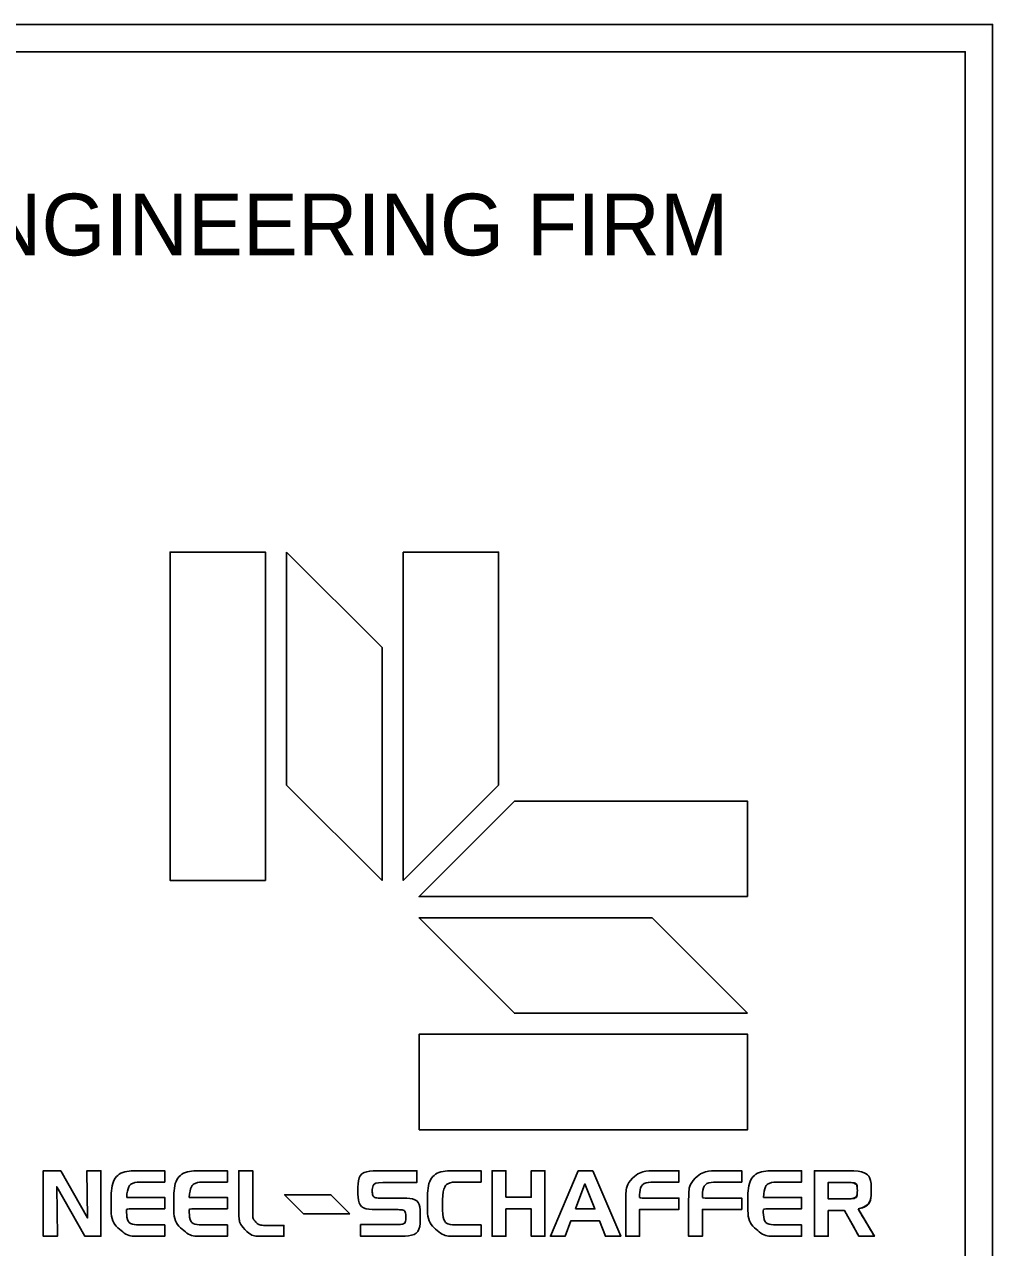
# Model space of a CAD drawing. Extents: x 1524103 to 2096450, y 1024229 to 1162569.
# Drawn here: x 2069965 to 2074608, y 1118769 to 1124635 of the extents above; entities that cross this region are included whole.
import ezdxf

# ---------------------------------------------------------------- set-up
doc = ezdxf.new("R2010")
doc.units = 0
for name, color, linetype in [('Default', 7, 'Continuous'), ('RD_SHT_Bndy', 7, 'Continuous'), ('RD_SHT_TX', 7, 'Continuous')]:
    doc.layers.add(name, color=color, linetype=linetype)

# ---------------------------------------------------------------- blocks, each defined once
blk = doc.blocks.new('block 3')
at = {"layer": 'Default'}
for p, q in [((-1.185, -5.553), (-1.185, -4.948)), ((-1.185, -4.948), (-1.024, -4.948)), ((-1.024, -4.948), (-0.776, -5.383)), ((-0.776, -5.383), (-0.782, -4.948)), ((-0.782, -4.948), (-0.653, -4.948)), ((-0.653, -4.948), (-0.653, -5.553)), ((2.958, -5.553), (2.958, -4.948)), ((2.958, -4.948), (3.085, -4.948)), ((3.085, -4.948), (3.085, -5.193)), ((3.318, -5.193), (3.318, -4.948)), ((3.318, -4.948), (3.445, -4.948)), ((3.445, -4.948), (3.445, -5.553)), ((3.496, -5.553), (3.752, -4.948)), ((3.752, -4.948), (3.887, -4.948)), ((3.887, -4.948), (4.145, -5.553)), ((3.814, -5.069), (3.726, -5.301)), ((3.906, -5.301), (3.814, -5.069)), ((-0.8, -5.553), (-1.06, -5.096)), ((-1.06, -5.096), (-1.054, -5.553)), ((1.47, -5.169), (1.042, -5.169)), ((1.042, -5.169), (1.217, -5.345)), ((1.646, -5.345), (1.47, -5.169)), ((3.085, -5.193), (3.318, -5.193)), ((3.318, -5.3), (3.085, -5.3)), ((3.085, -5.3), (3.085, -5.553)), ((3.318, -5.553), (3.318, -5.3)), ((3.726, -5.301), (3.906, -5.301)), ((1.217, -5.345), (1.646, -5.345)), ((3.685, -5.409), (3.631, -5.553)), ((3.948, -5.409), (3.685, -5.409)), ((4.003, -5.553), (3.948, -5.409)), ((-1.054, -5.553), (-1.185, -5.553)), ((-0.653, -5.553), (-0.8, -5.553)), ((3.085, -5.553), (2.958, -5.553)), ((3.445, -5.553), (3.318, -5.553)), ((3.631, -5.553), (3.496, -5.553)), ((4.145, -5.553), (4.003, -5.553))]:
    blk.add_line(p, q, dxfattribs=at)
for points in [[(-1.024, -4.948), (-0.776, -5.383), (-0.782, -4.948), (-0.653, -4.948), (-0.653, -5.553), (-0.8, -5.553), (-1.06, -5.096), (-1.054, -5.553), (-1.185, -5.553), (-1.185, -4.948), (-1.024, -4.948)], [(3.085, -5.193), (3.318, -5.193), (3.318, -4.948), (3.445, -4.948), (3.445, -5.553), (3.318, -5.553), (3.318, -5.3), (3.085, -5.3), (3.085, -5.553), (2.958, -5.553), (2.958, -4.948), (3.085, -4.948), (3.085, -5.193)], [(3.887, -4.948), (4.145, -5.553), (4.003, -5.553), (3.948, -5.409), (3.685, -5.409), (3.631, -5.553), (3.496, -5.553), (3.752, -4.948), (3.887, -4.948)], [(6.335, -5.3), (6.486, -5.553), (6.343, -5.553), (6.21, -5.315), (6.06, -5.315), (6.06, -5.553), (5.932, -5.553), (5.932, -4.948), (6.246, -4.948)], [(3.726, -5.301), (3.906, -5.301), (3.814, -5.069), (3.726, -5.301)], [(6.216, -5.056), (6.06, -5.056), (6.06, -5.208), (6.216, -5.208)], [(1.646, -5.345), (1.47, -5.169), (1.042, -5.169), (1.217, -5.345), (1.646, -5.345)]]:
    blk.add_lwpolyline(points, dxfattribs=at)
for points in [[(-0.415, -5.194), (-0.415, -5.194), (-0.063, -5.194), (-0.063, -5.194), (-0.063, -5.194), (-0.063, -5.299), (-0.063, -5.299), (-0.063, -5.299), (-0.416, -5.299), (-0.416, -5.299), (-0.415, -5.408), (-0.372, -5.448), (-0.272, -5.448), (-0.272, -5.448), (-0.063, -5.448), (-0.063, -5.448), (-0.063, -5.448), (-0.063, -5.553), (-0.063, -5.553), (-0.063, -5.553), (-0.278, -5.553), (-0.278, -5.553), (-0.351, -5.553), (-0.407, -5.547), (-0.466, -5.5), (-0.529, -5.45), (-0.559, -5.371), (-0.559, -5.262), (-0.559, -5.048), (-0.469, -4.948), (-0.274, -4.948), (-0.274, -4.948), (-0.063, -4.948), (-0.063, -4.948), (-0.063, -4.948), (-0.063, -5.053), (-0.063, -5.053), (-0.063, -5.053), (-0.272, -5.053), (-0.272, -5.053), (-0.364, -5.053), (-0.41, -5.099), (-0.415, -5.194)], [(-0.415, -5.194), (-0.415, -5.194), (-0.063, -5.194), (-0.063, -5.194), (-0.063, -5.194), (-0.063, -5.299), (-0.063, -5.299), (-0.063, -5.299), (-0.416, -5.299), (-0.416, -5.299), (-0.415, -5.408), (-0.372, -5.448), (-0.272, -5.448), (-0.272, -5.448), (-0.063, -5.448), (-0.063, -5.448), (-0.063, -5.448), (-0.063, -5.553), (-0.063, -5.553), (-0.063, -5.553), (-0.278, -5.553), (-0.278, -5.553), (-0.351, -5.553), (-0.407, -5.547), (-0.466, -5.5), (-0.529, -5.45), (-0.559, -5.371), (-0.559, -5.262), (-0.559, -5.048), (-0.469, -4.948), (-0.274, -4.948), (-0.274, -4.948), (-0.063, -4.948), (-0.063, -4.948), (-0.063, -4.948), (-0.063, -5.053), (-0.063, -5.053), (-0.063, -5.053), (-0.272, -5.053), (-0.272, -5.053), (-0.364, -5.053), (-0.41, -5.099), (-0.415, -5.194)], [(0.163, -5.194), (0.163, -5.194), (0.515, -5.194), (0.515, -5.194), (0.515, -5.194), (0.515, -5.299), (0.515, -5.299), (0.515, -5.299), (0.162, -5.299), (0.162, -5.299), (0.163, -5.408), (0.206, -5.448), (0.306, -5.448), (0.306, -5.448), (0.515, -5.448), (0.515, -5.448), (0.515, -5.448), (0.515, -5.553), (0.515, -5.553), (0.515, -5.553), (0.3, -5.553), (0.3, -5.553), (0.227, -5.553), (0.171, -5.547), (0.112, -5.5), (0.049, -5.45), (0.019, -5.371), (0.019, -5.262), (0.019, -5.048), (0.109, -4.948), (0.304, -4.948), (0.304, -4.948), (0.515, -4.948), (0.515, -4.948), (0.515, -4.948), (0.515, -5.053), (0.515, -5.053), (0.515, -5.053), (0.306, -5.053), (0.306, -5.053), (0.214, -5.053), (0.168, -5.099), (0.163, -5.194)], [(0.163, -5.194), (0.163, -5.194), (0.515, -5.194), (0.515, -5.194), (0.515, -5.194), (0.515, -5.299), (0.515, -5.299), (0.515, -5.299), (0.162, -5.299), (0.162, -5.299), (0.163, -5.408), (0.206, -5.448), (0.306, -5.448), (0.306, -5.448), (0.515, -5.448), (0.515, -5.448), (0.515, -5.448), (0.515, -5.553), (0.515, -5.553), (0.515, -5.553), (0.3, -5.553), (0.3, -5.553), (0.227, -5.553), (0.171, -5.547), (0.112, -5.5), (0.049, -5.45), (0.019, -5.371), (0.019, -5.262), (0.019, -5.048), (0.109, -4.948), (0.304, -4.948), (0.304, -4.948), (0.515, -4.948), (0.515, -4.948), (0.515, -4.948), (0.515, -5.053), (0.515, -5.053), (0.515, -5.053), (0.306, -5.053), (0.306, -5.053), (0.214, -5.053), (0.168, -5.099), (0.163, -5.194)], [(0.675, -5.49), (0.629, -5.441), (0.62, -5.388), (0.62, -5.308), (0.62, -5.308), (0.62, -4.948), (0.62, -4.948), (0.62, -4.948), (0.748, -4.948), (0.748, -4.948), (0.748, -4.948), (0.748, -5.28), (0.748, -5.28), (0.748, -5.288), (0.748, -5.296), (0.748, -5.304), (0.748, -5.353), (0.748, -5.39), (0.769, -5.413), (0.796, -5.445), (0.832, -5.453), (0.886, -5.453), (0.886, -5.453), (1.036, -5.453), (1.036, -5.453), (1.036, -5.453), (1.036, -5.553), (1.036, -5.553), (1.036, -5.553), (0.875, -5.553), (0.875, -5.553), (0.787, -5.553), (0.729, -5.547), (0.675, -5.49)], [(0.675, -5.49), (0.629, -5.441), (0.62, -5.388), (0.62, -5.308), (0.62, -5.308), (0.62, -4.948), (0.62, -4.948), (0.62, -4.948), (0.748, -4.948), (0.748, -4.948), (0.748, -4.948), (0.748, -5.28), (0.748, -5.28), (0.748, -5.288), (0.748, -5.296), (0.748, -5.304), (0.748, -5.353), (0.748, -5.39), (0.769, -5.413), (0.796, -5.445), (0.832, -5.453), (0.886, -5.453), (0.886, -5.453), (1.036, -5.453), (1.036, -5.453), (1.036, -5.453), (1.036, -5.553), (1.036, -5.553), (1.036, -5.553), (0.875, -5.553), (0.875, -5.553), (0.787, -5.553), (0.729, -5.547), (0.675, -5.49)], [(1.95, -5.056), (1.884, -5.056), (1.852, -5.08), (1.852, -5.135), (1.852, -5.179), (1.879, -5.201), (1.932, -5.201), (1.932, -5.201), (2.101, -5.201), (2.101, -5.201), (2.236, -5.201), (2.294, -5.245), (2.294, -5.372), (2.294, -5.499), (2.226, -5.553), (2.082, -5.553), (2.082, -5.553), (1.744, -5.553), (1.744, -5.553), (1.744, -5.553), (1.744, -5.445), (1.744, -5.445), (1.744, -5.445), (2.062, -5.445), (2.062, -5.445), (2.13, -5.445), (2.161, -5.429), (2.161, -5.377), (2.161, -5.323), (2.132, -5.307), (2.071, -5.307), (2.071, -5.307), (1.921, -5.307), (1.921, -5.307), (1.782, -5.307), (1.719, -5.255), (1.719, -5.133), (1.719, -5.002), (1.788, -4.948), (1.932, -4.948), (1.932, -4.948), (2.264, -4.948), (2.264, -4.948), (2.264, -4.948), (2.264, -5.056), (2.264, -5.056), (2.264, -5.056), (1.95, -5.056), (1.95, -5.056)], [(1.95, -5.056), (1.884, -5.056), (1.852, -5.08), (1.852, -5.135), (1.852, -5.179), (1.879, -5.201), (1.932, -5.201), (1.932, -5.201), (2.101, -5.201), (2.101, -5.201), (2.236, -5.201), (2.294, -5.245), (2.294, -5.372), (2.294, -5.499), (2.226, -5.553), (2.082, -5.553), (2.082, -5.553), (1.744, -5.553), (1.744, -5.553), (1.744, -5.553), (1.744, -5.445), (1.744, -5.445), (1.744, -5.445), (2.062, -5.445), (2.062, -5.445), (2.13, -5.445), (2.161, -5.429), (2.161, -5.377), (2.161, -5.323), (2.132, -5.307), (2.071, -5.307), (2.071, -5.307), (1.921, -5.307), (1.921, -5.307), (1.782, -5.307), (1.719, -5.255), (1.719, -5.133), (1.719, -5.002), (1.788, -4.948), (1.932, -4.948), (1.932, -4.948), (2.264, -4.948), (2.264, -4.948), (2.264, -4.948), (2.264, -5.056), (2.264, -5.056), (2.264, -5.056), (1.95, -5.056), (1.95, -5.056)], [(2.499, -5.267), (2.499, -5.402), (2.54, -5.448), (2.647, -5.448), (2.647, -5.448), (2.856, -5.448), (2.856, -5.448), (2.856, -5.448), (2.856, -5.553), (2.856, -5.553), (2.856, -5.553), (2.641, -5.553), (2.641, -5.553), (2.568, -5.553), (2.511, -5.547), (2.452, -5.5), (2.39, -5.45), (2.36, -5.371), (2.36, -5.262), (2.36, -5.048), (2.45, -4.948), (2.644, -4.948), (2.644, -4.948), (2.856, -4.948), (2.856, -4.948), (2.856, -4.948), (2.856, -5.052), (2.856, -5.052), (2.856, -5.052), (2.647, -5.052), (2.647, -5.052), (2.54, -5.052), (2.499, -5.117), (2.499, -5.267)], [(2.499, -5.267), (2.499, -5.402), (2.54, -5.448), (2.647, -5.448), (2.647, -5.448), (2.856, -5.448), (2.856, -5.448), (2.856, -5.448), (2.856, -5.553), (2.856, -5.553), (2.856, -5.553), (2.641, -5.553), (2.641, -5.553), (2.568, -5.553), (2.511, -5.547), (2.452, -5.5), (2.39, -5.45), (2.36, -5.371), (2.36, -5.262), (2.36, -5.048), (2.45, -4.948), (2.644, -4.948), (2.644, -4.948), (2.856, -4.948), (2.856, -4.948), (2.856, -4.948), (2.856, -5.052), (2.856, -5.052), (2.856, -5.052), (2.647, -5.052), (2.647, -5.052), (2.54, -5.052), (2.499, -5.117), (2.499, -5.267)], [(4.253, -5.017), (4.3, -4.969), (4.376, -4.948), (4.488, -4.948), (4.488, -4.948), (4.682, -4.948), (4.682, -4.948), (4.682, -4.948), (4.682, -5.053), (4.682, -5.053), (4.682, -5.053), (4.477, -5.053), (4.477, -5.053), (4.369, -5.053), (4.32, -5.096), (4.318, -5.201), (4.318, -5.201), (4.682, -5.201), (4.682, -5.201), (4.682, -5.201), (4.682, -5.305), (4.682, -5.305), (4.682, -5.305), (4.318, -5.305), (4.318, -5.305), (4.318, -5.305), (4.318, -5.553), (4.318, -5.553), (4.318, -5.553), (4.191, -5.553), (4.191, -5.553), (4.191, -5.553), (4.191, -5.275), (4.191, -5.275), (4.191, -5.155), (4.198, -5.073), (4.253, -5.017)], [(4.253, -5.017), (4.3, -4.969), (4.376, -4.948), (4.488, -4.948), (4.488, -4.948), (4.682, -4.948), (4.682, -4.948), (4.682, -4.948), (4.682, -5.053), (4.682, -5.053), (4.682, -5.053), (4.477, -5.053), (4.477, -5.053), (4.369, -5.053), (4.32, -5.096), (4.318, -5.201), (4.318, -5.201), (4.682, -5.201), (4.682, -5.201), (4.682, -5.201), (4.682, -5.305), (4.682, -5.305), (4.682, -5.305), (4.318, -5.305), (4.318, -5.305), (4.318, -5.305), (4.318, -5.553), (4.318, -5.553), (4.318, -5.553), (4.191, -5.553), (4.191, -5.553), (4.191, -5.553), (4.191, -5.275), (4.191, -5.275), (4.191, -5.155), (4.198, -5.073), (4.253, -5.017)], [(4.832, -5.017), (4.879, -4.969), (4.956, -4.948), (5.068, -4.948), (5.068, -4.948), (5.262, -4.948), (5.262, -4.948), (5.262, -4.948), (5.262, -5.053), (5.262, -5.053), (5.262, -5.053), (5.057, -5.053), (5.057, -5.053), (4.948, -5.053), (4.9, -5.096), (4.898, -5.201), (4.898, -5.201), (5.262, -5.201), (5.262, -5.201), (5.262, -5.201), (5.262, -5.305), (5.262, -5.305), (5.262, -5.305), (4.898, -5.305), (4.898, -5.305), (4.898, -5.305), (4.898, -5.553), (4.898, -5.553), (4.898, -5.553), (4.771, -5.553), (4.771, -5.553), (4.771, -5.553), (4.771, -5.275), (4.771, -5.275), (4.771, -5.155), (4.777, -5.073), (4.832, -5.017)], [(4.832, -5.017), (4.879, -4.969), (4.956, -4.948), (5.068, -4.948), (5.068, -4.948), (5.262, -4.948), (5.262, -4.948), (5.262, -4.948), (5.262, -5.053), (5.262, -5.053), (5.262, -5.053), (5.057, -5.053), (5.057, -5.053), (4.948, -5.053), (4.9, -5.096), (4.898, -5.201), (4.898, -5.201), (5.262, -5.201), (5.262, -5.201), (5.262, -5.201), (5.262, -5.305), (5.262, -5.305), (5.262, -5.305), (4.898, -5.305), (4.898, -5.305), (4.898, -5.305), (4.898, -5.553), (4.898, -5.553), (4.898, -5.553), (4.771, -5.553), (4.771, -5.553), (4.771, -5.553), (4.771, -5.275), (4.771, -5.275), (4.771, -5.155), (4.777, -5.073), (4.832, -5.017)], [(5.461, -5.194), (5.461, -5.194), (5.813, -5.194), (5.813, -5.194), (5.813, -5.194), (5.813, -5.299), (5.813, -5.299), (5.813, -5.299), (5.46, -5.299), (5.46, -5.299), (5.461, -5.408), (5.504, -5.448), (5.604, -5.448), (5.604, -5.448), (5.813, -5.448), (5.813, -5.448), (5.813, -5.448), (5.813, -5.553), (5.813, -5.553), (5.813, -5.553), (5.598, -5.553), (5.598, -5.553), (5.525, -5.553), (5.468, -5.547), (5.409, -5.5), (5.347, -5.45), (5.317, -5.371), (5.317, -5.262), (5.317, -5.048), (5.407, -4.948), (5.601, -4.948), (5.601, -4.948), (5.813, -4.948), (5.813, -4.948), (5.813, -4.948), (5.813, -5.053), (5.813, -5.053), (5.813, -5.053), (5.604, -5.053), (5.604, -5.053), (5.512, -5.053), (5.466, -5.099), (5.461, -5.194)], [(5.461, -5.194), (5.461, -5.194), (5.813, -5.194), (5.813, -5.194), (5.813, -5.194), (5.813, -5.299), (5.813, -5.299), (5.813, -5.299), (5.46, -5.299), (5.46, -5.299), (5.461, -5.408), (5.504, -5.448), (5.604, -5.448), (5.604, -5.448), (5.813, -5.448), (5.813, -5.448), (5.813, -5.448), (5.813, -5.553), (5.813, -5.553), (5.813, -5.553), (5.598, -5.553), (5.598, -5.553), (5.525, -5.553), (5.468, -5.547), (5.409, -5.5), (5.347, -5.45), (5.317, -5.371), (5.317, -5.262), (5.317, -5.048), (5.407, -4.948), (5.601, -4.948), (5.601, -4.948), (5.813, -4.948), (5.813, -4.948), (5.813, -4.948), (5.813, -5.053), (5.813, -5.053), (5.813, -5.053), (5.604, -5.053), (5.604, -5.053), (5.512, -5.053), (5.466, -5.099), (5.461, -5.194)], [(6.246, -4.948), (6.389, -4.948), (6.457, -5.003), (6.457, -5.13), (6.457, -5.224), (6.413, -5.283), (6.335, -5.3), (6.335, -5.3), (6.486, -5.553), (6.486, -5.553), (6.486, -5.553), (6.343, -5.553), (6.343, -5.553), (6.343, -5.553), (6.21, -5.315), (6.21, -5.315), (6.21, -5.315), (6.06, -5.315), (6.06, -5.315), (6.06, -5.315), (6.06, -5.553), (6.06, -5.553), (6.06, -5.553), (5.932, -5.553), (5.932, -5.553), (5.932, -5.553), (5.932, -4.948), (5.932, -4.948), (5.932, -4.948), (6.246, -4.948), (6.246, -4.948)], [(6.246, -4.948), (6.389, -4.948), (6.457, -5.003), (6.457, -5.13), (6.457, -5.224), (6.413, -5.283), (6.335, -5.3)], [(6.06, -5.056), (6.06, -5.056), (6.06, -5.208), (6.06, -5.208), (6.06, -5.208), (6.216, -5.208), (6.216, -5.208), (6.291, -5.208), (6.328, -5.193), (6.328, -5.132), (6.328, -5.069), (6.291, -5.056), (6.216, -5.056), (6.216, -5.056), (6.06, -5.056), (6.06, -5.056)], [(6.216, -5.208), (6.291, -5.208), (6.328, -5.193), (6.328, -5.132), (6.328, -5.069), (6.291, -5.056), (6.216, -5.056)]]:
    blk.add_open_spline(points, degree=3, dxfattribs=at)
blk = doc.blocks.new('block 2')
at = {"layer": 'Default'}
for p, q in [((-0.014, -2.269), (-0.014, 0.762)), ((-0.014, 0.762), (0.866, 0.762)), ((0.866, 0.762), (0.866, -2.269)), ((1.061, 0.762), (1.942, -0.118)), ((1.061, -1.389), (1.061, 0.762)), ((2.137, 0.762), (3.017, 0.762)), ((2.137, -2.269), (2.137, 0.762)), ((3.017, 0.762), (3.017, -1.389)), ((1.942, -0.118), (1.942, -2.269)), ((1.942, -2.269), (1.061, -1.389)), ((3.017, -1.389), (2.137, -2.269)), ((3.164, -1.538), (2.284, -2.418)), ((5.315, -1.538), (3.164, -1.538)), ((5.315, -2.418), (5.315, -1.538)), ((0.866, -2.269), (-0.014, -2.269)), ((2.284, -2.418), (5.315, -2.418)), ((4.435, -2.614), (2.284, -2.614)), ((2.284, -2.614), (3.164, -3.494)), ((5.315, -3.494), (4.435, -2.614)), ((3.164, -3.494), (5.315, -3.494)), ((5.315, -3.689), (2.284, -3.689)), ((2.284, -3.689), (2.284, -4.569)), ((5.315, -4.569), (5.315, -3.689)), ((2.284, -4.569), (5.315, -4.569))]:
    blk.add_line(p, q, dxfattribs=at)
for points in [[(0.866, -2.269), (-0.014, -2.269), (-0.014, 0.762), (0.866, 0.762), (0.866, -2.269)], [(1.061, 0.762), (1.942, -0.118), (1.942, -2.269), (1.061, -1.389), (1.061, 0.762)], [(2.137, 0.762), (3.017, 0.762), (3.017, -1.389), (2.137, -2.269), (2.137, 0.762)], [(5.315, -2.418), (5.315, -1.538), (3.164, -1.538), (2.284, -2.418), (5.315, -2.418)], [(5.315, -3.494), (4.435, -2.614), (2.284, -2.614), (3.164, -3.494), (5.315, -3.494)], [(2.284, -4.569), (5.315, -4.569), (5.315, -3.689), (2.284, -3.689), (2.284, -4.569)]]:
    blk.add_lwpolyline(points, dxfattribs=at)
blk.add_blockref('block 3', (0, 0), dxfattribs=at)

msp = doc.modelspace()

# ---------------------------------------------------------------- linework, layer by layer
at = {"layer": 'RD_SHT_Bndy'}
for points in [[(2065606.8, 1117100.8), (2074607.6, 1117100.8), (2074607.6, 1124635.2), (2065606.8, 1124635.2)], [(2065737.6, 1117227.6), (2074476.9, 1117227.6), (2074476.9, 1124504.5), (2065737.6, 1124504.5)]]:
    msp.add_lwpolyline(points, close=True, dxfattribs=at)

# ---------------------------------------------------------------- block references
at = {"layer": 'RD_SHT_Bndy', "xscale": 519.7070658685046, "yscale": 519.7070658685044, "rotation": 2.585745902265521e-11}
msp.add_blockref('block 2', (2070670.5, 1121708.7), dxfattribs=at)

# ---------------------------------------------------------------- texts
at = {"layer": 'RD_SHT_TX'}
for height, p in [(295.68, (2066794.5, 1123527.9)), (295.692, (2066794.6, 1123527.8))]:
    msp.add_text('CONSULTING ENGINEERING FIRM', height=height, dxfattribs=at).set_placement(p)

doc.saveas('drawing.dxf')
